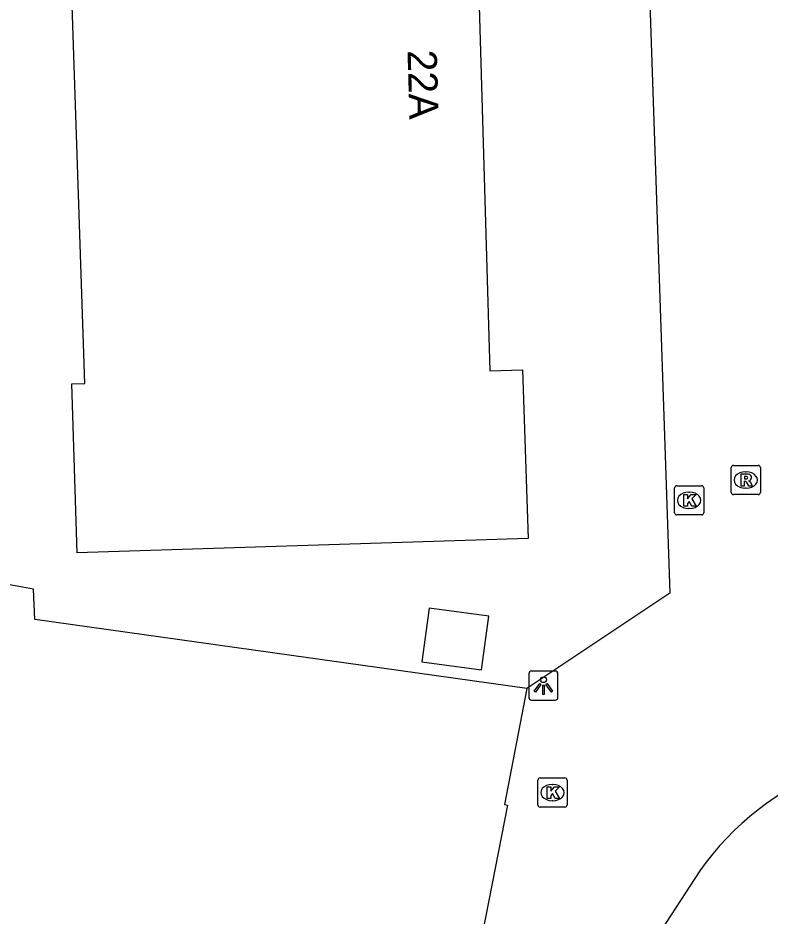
# Model space of a CAD drawing. Extents: x 161402 to 161933, y 381650 to 382313.
# Drawn here: x 161864.17 to 161889.94, y 382075.91 to 382106.69 of the extents above; entities that cross this region are included whole.
import ezdxf

# ---------------------------------------------------------------- set-up
doc = ezdxf.new("R2010")
doc.units = 0
for name, color, linetype in [('IMGEO_Kolk', 7, 'Continuous'), ('IMGEO_Lage_trafo', 7, 'Continuous'), ('IMGEO_Lichtpunt', 7, 'Continuous'), ('IMGEO_Pand', 7, 'Continuous'), ('IMGEO_Pand_nummerreeks', 7, 'Continuous'), ('IMGEO_Rijbaan_lokaal_open', 7, 'Continuous'), ('IMGEO_Rioolput', 7, 'Continuous')]:
    doc.layers.add(name, color=color, linetype=linetype)

msp = doc.modelspace()

# ---------------------------------------------------------------- linework, layer by layer
at = {"layer": 'IMGEO_Kolk'}
for p, q in [((161886.667, 382089.728), (161886.667, 382090.58)), ((161886.742, 382090.654), (161887.594, 382090.654)), ((161887.668, 382090.58), (161887.668, 382089.728)), ((161887.155, 382090.434), (161887.18, 382090.434)), ((161887.594, 382089.654), (161886.742, 382089.654)), ((161887.178, 382089.874), (161887.153, 382089.874)), ((161881.984, 382079.714), (161881.984, 382080.566)), ((161882.059, 382080.64), (161882.911, 382080.64)), ((161882.472, 382080.42), (161882.497, 382080.42)), ((161882.985, 382080.566), (161882.985, 382079.714)), ((161882.495, 382079.86), (161882.47, 382079.86)), ((161882.911, 382079.64), (161882.059, 382079.64))]:
    msp.add_line(p, q, dxfattribs=at)
for points in [[(161886.667, 382089.728), (161886.667, 382090.58)], [(161886.742, 382090.654), (161887.594, 382090.654)], [(161887.668, 382090.58), (161887.668, 382089.728)], [(161886.988, 382090.354), (161887.111, 382090.354), (161887.111, 382090.203), (161887.241, 382090.354), (161887.405, 382090.354), (161887.259, 382090.203), (161887.412, 382089.954), (161887.26, 382089.954), (161887.175, 382090.118), (161887.111, 382090.051), (161887.111, 382089.954), (161886.988, 382089.954), (161886.988, 382090.354)], [(161887.594, 382089.654), (161886.742, 382089.654)], [(161881.984, 382079.714), (161881.984, 382080.566)], [(161882.059, 382080.64), (161882.911, 382080.64)], [(161882.985, 382080.566), (161882.985, 382079.714)], [(161882.305, 382080.34), (161882.428, 382080.34), (161882.428, 382080.189), (161882.558, 382080.34), (161882.722, 382080.34), (161882.576, 382080.189), (161882.729, 382079.94), (161882.577, 382079.94), (161882.492, 382080.104), (161882.428, 382080.037), (161882.428, 382079.94), (161882.305, 382079.94), (161882.305, 382080.34)], [(161882.911, 382079.64), (161882.059, 382079.64)]]:
    msp.add_lwpolyline(points, dxfattribs=at)
for centre, start, end in [((161886.744, 382090.578), 91.552, 178.448), ((161886.744, 382090.578), 91.552, 178.448), ((161887.592, 382090.578), 1.552, 88.448), ((161887.592, 382090.578), 1.552, 88.448), ((161886.744, 382089.73), 181.552, 268.448), ((161886.744, 382089.73), 181.552, 268.448), ((161887.592, 382089.73), 271.552, 358.448), ((161887.592, 382089.73), 271.552, 358.448), ((161882.061, 382080.564), 91.552, 178.448), ((161882.061, 382080.564), 91.552, 178.448), ((161882.909, 382080.564), 1.552, 88.448), ((161882.909, 382080.564), 1.552, 88.448), ((161882.061, 382079.716), 181.552, 268.448), ((161882.061, 382079.716), 181.552, 268.448), ((161882.909, 382079.716), 271.552, 358.448), ((161882.909, 382079.716), 271.552, 358.448)]:
    msp.add_arc(centre, 0.0765, start, end, dxfattribs=at)
for centre, major_axis, ratio, start_param, end_param in [((161887.154, 382090.154), (-0.387, 0.002), 0.722429, 4.712389, 7.853982), ((161887.179, 382090.154), (-0.39, 0.002), 0.717154, 1.570796, 4.712389), ((161882.471, 382080.14), (-0.387, 0.002), 0.722429, 4.712389, 7.853982), ((161882.496, 382080.14), (-0.39, 0.002), 0.717154, 1.570796, 4.712389)]:
    msp.add_ellipse(centre, major_axis=major_axis, ratio=ratio, start_param=start_param, end_param=end_param, dxfattribs=at)
at = {"layer": 'IMGEO_Lage_trafo'}
msp.add_lwpolyline([(161880.304, 382086.186), (161878.262, 382086.461), (161878.009, 382084.619), (161880.05, 382084.343), (161880.304, 382086.186)], dxfattribs=at)
at = {"layer": 'IMGEO_Lichtpunt'}
for p, q in [((161881.677, 382084.21), (161881.677, 382083.403)), ((161881.677, 382084.21), (161881.677, 382083.403)), ((161882.579, 382084.305), (161881.771, 382084.305)), ((161882.579, 382084.305), (161881.771, 382084.305)), ((161882.673, 382083.403), (161882.673, 382084.21)), ((161882.673, 382083.403), (161882.673, 382084.21)), ((161881.771, 382083.309), (161882.579, 382083.309)), ((161881.771, 382083.309), (161882.579, 382083.309))]:
    msp.add_line(p, q, dxfattribs=at)
for points in [[(161882.051, 382083.874), (161882.09, 382083.846), (161881.902, 382083.584), (161881.864, 382083.611), (161882.051, 382083.874)], [(161882.153, 382083.826), (161882.2, 382083.826), (161882.2, 382083.504), (161882.153, 382083.504), (161882.153, 382083.826)], [(161882.263, 382083.846), (161882.301, 382083.873), (161882.488, 382083.611), (161882.449, 382083.583), (161882.263, 382083.846)]]:
    msp.add_lwpolyline(points, dxfattribs=at)
msp.add_circle((161882.176, 382084.008), 0.0994, dxfattribs=at)
for centre, start, end in [((161881.771, 382084.21), 90, 180), ((161881.771, 382084.21), 90, 180), ((161882.579, 382084.21), 0, 90), ((161882.579, 382084.21), 0, 90), ((161881.771, 382083.403), 180, 270), ((161881.771, 382083.403), 180, 270), ((161882.579, 382083.403), 270, 0), ((161882.579, 382083.403), 270, 360)]:
    msp.add_arc(centre, 0.0946, start, end, dxfattribs=at)
at = {"layer": 'IMGEO_Pand'}
for points in [[(161875.799, 382120.848), (161875.926, 382116.75), (161879.684, 382116.866), (161880.342, 382094.587), (161881.463, 382094.624), (161881.653, 382088.841), (161866.197, 382088.354), (161866.014, 382094.144), (161866.456, 382094.154), (161865.684, 382117.343), (161865.575, 382120.533), (161875.799, 382120.848)], [(161881.604, 382083.709), (161864.747, 382086.071), (161864.705, 382087.108), (161857.022, 382088.5), (161857.282, 382089.936), (161856.514, 382090.075), (161856.605, 382090.577), (161849.637, 382091.837)], [(161881.604, 382083.709), (161880.846, 382079.728), (161880.941, 382079.709), (161879.984, 382074.802), (161879.866, 382074.825), (161879.674, 382073.772), (161879.777, 382073.754), (161876.327, 382055.897), (161876.056, 382054.517), (161875.966, 382054.535), (161874.803, 382048.597), (161867.831, 382049.852)]]:
    msp.add_lwpolyline(points, dxfattribs=at)
at = {"layer": 'IMGEO_Rijbaan_lokaal_open'}
for points in [[(161863.229, 382133.182), (161872.557, 382142.66), (161885.051, 382130.105), (161886.502, 382086.978), (161881.604, 382083.709)], [(161887.537, 382077.461), (161885.72, 382074.668)]]:
    msp.add_lwpolyline(points, dxfattribs=at)
msp.add_arc((161895.614, 382071.735), 9.901, 111.1686, 144.6677, dxfattribs=at)
at = {"layer": 'IMGEO_Rioolput'}
for p, q in [((161888.609, 382090.424), (161888.609, 382091.276)), ((161888.684, 382091.35), (161889.536, 382091.35)), ((161889.097, 382091.13), (161889.122, 382091.13)), ((161889.61, 382091.276), (161889.61, 382090.424)), ((161889.12, 382090.57), (161889.095, 382090.57)), ((161889.536, 382090.35), (161888.684, 382090.35))]:
    msp.add_line(p, q, dxfattribs=at)
for points in [[(161888.609, 382090.424), (161888.609, 382091.276)], [(161888.684, 382091.35), (161889.536, 382091.35)], [(161889.61, 382091.276), (161889.61, 382090.424)], [(161889.198, 382091.048), (161888.946, 382091.05), (161888.946, 382090.65)], [(161888.946, 382090.65), (161889.07, 382090.65), (161889.07, 382090.812), (161889.081, 382090.812)], [(161889.124, 382090.969), (161889.07, 382090.969), (161889.07, 382090.888)], [(161889.07, 382090.888), (161889.122, 382090.888)], [(161889.128, 382090.783), (161889.199, 382090.65), (161889.339, 382090.65), (161889.274, 382090.776)], [(161889.536, 382090.35), (161888.684, 382090.35)]]:
    msp.add_lwpolyline(points, dxfattribs=at)
for centre, radius, start, end in [((161888.686, 382091.274), 0.0765, 91.552, 178.448), ((161888.686, 382091.274), 0.0765, 91.552, 178.448), ((161889.534, 382091.274), 0.0765, 1.552, 88.448), ((161889.534, 382091.274), 0.0765, 1.552, 88.448), ((161889.08, 382090.759), 0.0533, 26.0293, 88.6989), ((161889.106, 382091.077), 0.19, 274.7715, 282.9687), ((161889.13, 382090.873), 0.0964, 77.0061, 93.1865), ((161889.144, 382090.93), 0.0378, 276.6634, 79.6772), ((161889.197, 382090.938), 0.109, 350.3612, 89.416), ((161889.195, 382090.938), 0.112, 277.5842, 350.9817), ((161889.179, 382090.723), 0.108, 29.5134, 73.7905), ((161888.686, 382090.426), 0.0765, 181.552, 268.448), ((161888.686, 382090.426), 0.0765, 181.552, 268.448), ((161889.534, 382090.426), 0.0765, 271.552, 358.448), ((161889.534, 382090.426), 0.0765, 271.552, 358.448)]:
    msp.add_arc(centre, radius, start, end, dxfattribs=at)
for centre, major_axis, ratio, start_param, end_param in [((161889.096, 382090.85), (-0.387, 0.002), 0.722429, 4.712389, 7.853982), ((161889.121, 382090.85), (-0.39, 0.002), 0.717154, 1.570796, 4.712389)]:
    msp.add_ellipse(centre, major_axis=major_axis, ratio=ratio, start_param=start_param, end_param=end_param, dxfattribs=at)

# ---------------------------------------------------------------- texts
at = {"layer": 'IMGEO_Pand_nummerreeks'}
msp.add_text('22A', height=1, rotation=271.69, dxfattribs=at).set_placement((161877.516, 382105.578))

doc.saveas('drawing.dxf')
